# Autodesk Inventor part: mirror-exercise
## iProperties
Author: Administrator
Created: 2000-12
Part Number: mirror-exercise
Document SubType Name: Modeling
Designer: Administrator
Control State: 0
Master: False
Checked Out: False
PropertySet Name: Design Tracking Control
Shininess: 0.0
PropertySet Name: _Private Model Information
Density: 0.0
Volumn: 0.0
Area: 0.0
PropertySet Name: Model Information
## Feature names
1. Extrusion1
